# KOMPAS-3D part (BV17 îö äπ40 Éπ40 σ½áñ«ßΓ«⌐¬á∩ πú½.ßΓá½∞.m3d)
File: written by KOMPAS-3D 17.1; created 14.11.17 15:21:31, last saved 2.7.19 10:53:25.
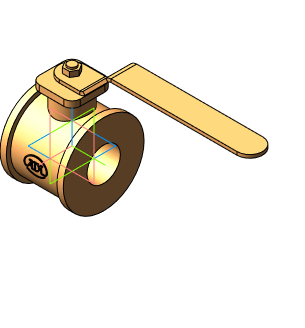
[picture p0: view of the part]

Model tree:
1. Операция без истории:2  (labels: Сталь 20  ГОСТ 1050-2013)

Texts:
  Толщина листового тела
  Глубина освобождения сгиба
  Ширина освобождения сгиба
  BV17 МФ Ду15 Ру40 хладостойкая угл.сталь
  BV17 МФ Ду20 Ру40 хладостойкая угл.сталь
  BV17 МФ Ду25 Ру40 хладостойкая угл.сталь
  BV17 МФ Ду32 Ру40 хладостойкая угл.сталь
  BV17 МФ Ду40 Ру40 хладостойкая угл.сталь
  BV17 МФ Ду50 Ру40 хладостойкая угл.сталь
  BV17 МФ Ду65 Ру40 хладостойкая угл.сталь
  BV17 МФ Ду80 Ру40 хладостойкая угл.сталь
  BV17 МФ Ду100 Ру40 хладостойкая угл.сталь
